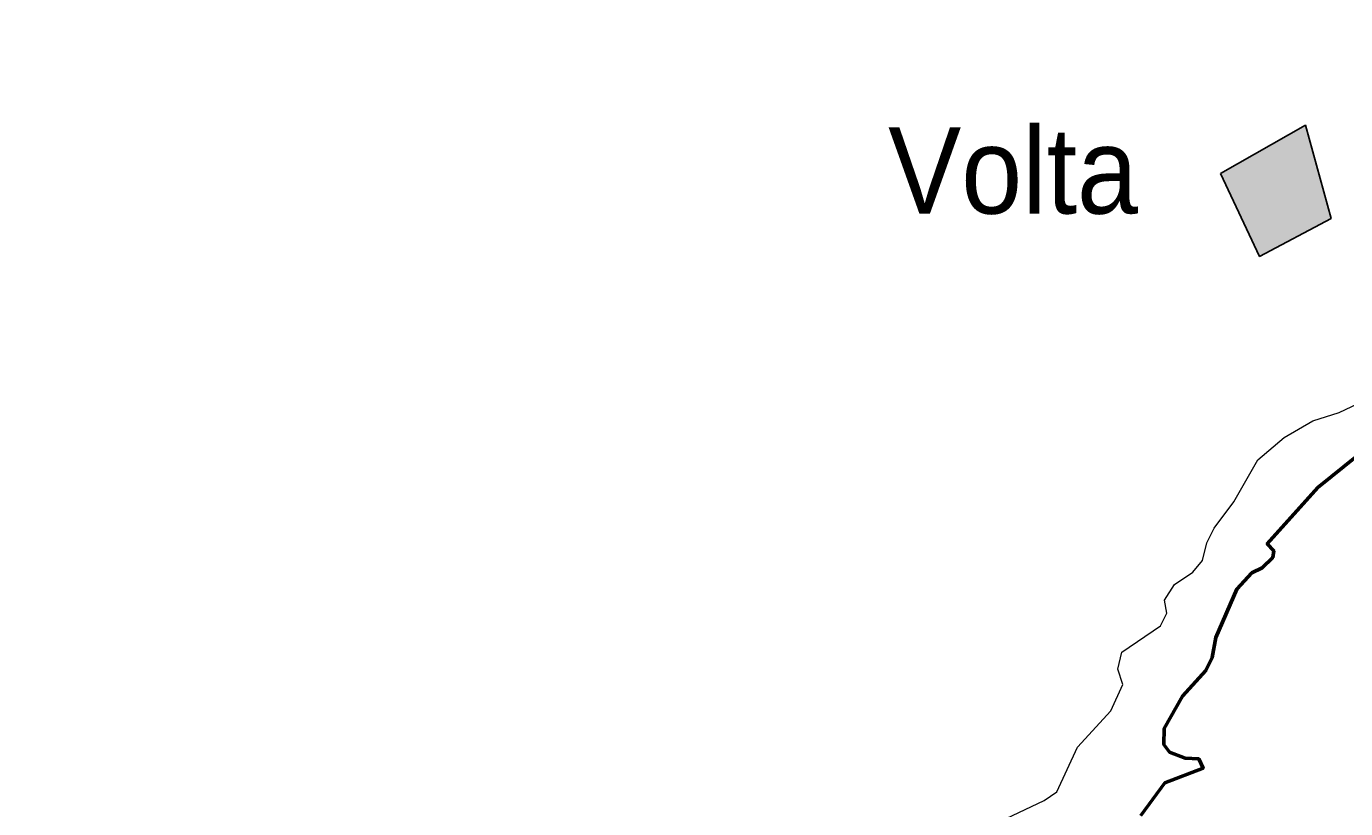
# Model space of a CAD drawing. Extents: x -1643653 to 4543381, y 1624270 to 13878484.
# Drawn here: x 584467 to 592113, y 8973351 to 8977882 of the extents above; entities that cross this region are included whole.
import ezdxf

# ---------------------------------------------------------------- set-up
doc = ezdxf.new("R2010")
doc.units = 0
doc.header["$LTSCALE"] = 200
for name, color, linetype, lineweight in [('1', 7, 'Continuous', 13), ('21', 7, 'Continuous', 25), ('25', 7, 'Continuous', 13), ('27', 7, 'Continuous', 53), ('28', 7, 'Continuous', 53)]:
    doc.layers.add(name, color=color, linetype=linetype, lineweight=lineweight)
doc.layers.add('41', color=7, linetype='Continuous')

msp = doc.modelspace()

# ---------------------------------------------------------------- hatches: boundary and pattern name
at = {"layer": '21'}
msp.add_hatch(color=256, dxfattribs=at).paths.add_polyline_path([(591387.2, 8977029.8), (591614.3, 8976550.1), (592028.7, 8976768.6), (591880.1, 8977309.9)])

# ---------------------------------------------------------------- linework, layer by layer
at = {"layer": '1', "lineweight": 25}
msp.add_spline([(814781, 9009175.5), (814787.2, 9009173.4), (814796.9, 9009173.4), (814799.4, 9009172.4), (814805.1, 9009174.5), (814805.6, 9009176.5), (814811.7, 9009179.5), (814811.7, 9009179.5), (814801.5, 9009181), (814790.7, 9009181.5), (814784.1, 9009183.1), (814777.4, 9009185.1), (814778.4, 9009175.5)], degree=3, dxfattribs=at)
at = {"layer": '21'}
msp.add_lwpolyline([(591387.2, 8977029.8), (591614.3, 8976550.1), (592028.7, 8976768.6), (591880.1, 8977309.9)], close=True, dxfattribs=at)
at = {"layer": '25'}
for points in [[(589783.1, 8973121.1), (590364.9, 8973397.1), (590439.2, 8973448.1), (590558.2, 8973707.2), (590751.6, 8973917.8), (590821.5, 8974070.5), (590792, 8974157.8), (590815.2, 8974257.2), (591040.4, 8974410.4), (591076.5, 8974482.4), (591063.8, 8974558.8), (591121.2, 8974648.3), (591227.2, 8974720.4), (591282.6, 8974788.8), (591308.2, 8974890.7), (591350.1, 8974974.6), (591465.3, 8975128.4), (591603.2, 8975370.3), (591756.1, 8975500), (591922, 8975597.8), (592075.7, 8975644.8), (592185.6, 8975697.8)], [(589783.1, 8973121.1), (590364.9, 8973397.1), (590439.2, 8973448.1), (590558.2, 8973707.2), (590751.6, 8973917.8), (590821.5, 8974070.5), (590792, 8974157.8), (590815.2, 8974257.2), (591040.4, 8974410.4), (591076.5, 8974482.4), (591063.8, 8974558.8), (591121.2, 8974648.3), (591227.2, 8974720.4), (591282.6, 8974788.8), (591308.2, 8974890.7), (591350.1, 8974974.6), (591465.3, 8975128.4), (591603.2, 8975370.3), (591756.1, 8975500), (591922, 8975597.8), (592075.7, 8975644.8), (592185.6, 8975697.8)], [(592178.8, 8975393.7), (591951.5, 8975211), (591658.9, 8974884.4), (591696.9, 8974843.5), (591690.4, 8974805.5), (591629, 8974746.2), (591569.4, 8974716.2), (591482.2, 8974622.5), (591361.3, 8974342.6), (591339.9, 8974225.6), (591302.4, 8974150.2), (591167.7, 8974002.3), (591061.7, 8973815.6), (591059.6, 8973722.4), (591091.3, 8973677.8), (591182.8, 8973643.6), (591261.3, 8973639.2), (591286.8, 8973584.3), (591065.8, 8973500.9), (590925.8, 8973310)], [(592178.8, 8975393.7), (591951.5, 8975211), (591658.9, 8974884.4), (591696.9, 8974843.5), (591690.4, 8974805.5), (591629, 8974746.2), (591569.4, 8974716.2), (591482.2, 8974622.5), (591361.3, 8974342.6), (591339.9, 8974225.6), (591302.4, 8974150.2), (591167.7, 8974002.3), (591061.7, 8973815.6), (591059.6, 8973722.4), (591091.3, 8973677.8), (591182.8, 8973643.6), (591261.3, 8973639.2), (591286.8, 8973584.3), (591065.8, 8973500.9), (590925.8, 8973310)]]:
    msp.add_lwpolyline(points, dxfattribs=at)
at = {"layer": '27'}
msp.add_lwpolyline([(590925.8, 8973310), (591065.8, 8973500.9), (591286.8, 8973584.3), (591261.3, 8973639.2), (591182.8, 8973643.6), (591091.3, 8973677.8), (591059.6, 8973722.4), (591061.7, 8973815.6), (591167.7, 8974002.3), (591302.4, 8974150.2), (591339.9, 8974225.6), (591361.3, 8974342.6), (591482.2, 8974622.5), (591569.4, 8974716.2), (591629, 8974746.2), (591690.4, 8974805.5), (591696.9, 8974843.5), (591658.9, 8974884.4), (591951.5, 8975211), (592178.8, 8975393.7)], dxfattribs=at)
at = {"layer": '28'}
msp.add_lwpolyline([(592178.8, 8975393.7), (591951.5, 8975211), (591658.9, 8974884.4), (591696.9, 8974843.5), (591690.4, 8974805.5), (591629, 8974746.2), (591569.4, 8974716.2), (591482.2, 8974622.5), (591361.3, 8974342.6), (591339.9, 8974225.6), (591302.4, 8974150.2), (591167.7, 8974002.3), (591061.7, 8973815.6), (591059.6, 8973722.4), (591091.3, 8973677.8), (591182.8, 8973643.6), (591261.3, 8973639.2), (591286.8, 8973584.3), (591065.8, 8973500.9), (590925.8, 8973310)], dxfattribs=at)
msp.add_lwpolyline([(592178.8, 8975393.7), (591951.5, 8975211), (591658.9, 8974884.4), (591696.9, 8974843.5), (591690.4, 8974805.5), (591629, 8974746.2), (591569.4, 8974716.2), (591482.2, 8974622.5), (591361.3, 8974342.6), (591339.9, 8974225.6), (591302.4, 8974150.2), (591167.7, 8974002.3), (591061.7, 8973815.6), (591059.6, 8973722.4), (591091.3, 8973677.8), (591182.8, 8973643.6), (591261.3, 8973639.2), (591286.8, 8973584.3), (591065.8, 8973500.9), (590925.8, 8973310)], dxfattribs=at)

# ---------------------------------------------------------------- texts
at = {"layer": '41', "width": 0.95}
msp.add_text('Volta', height=500, dxfattribs=at).set_placement((589461.3, 8976797.6))

doc.saveas('drawing.dxf')
